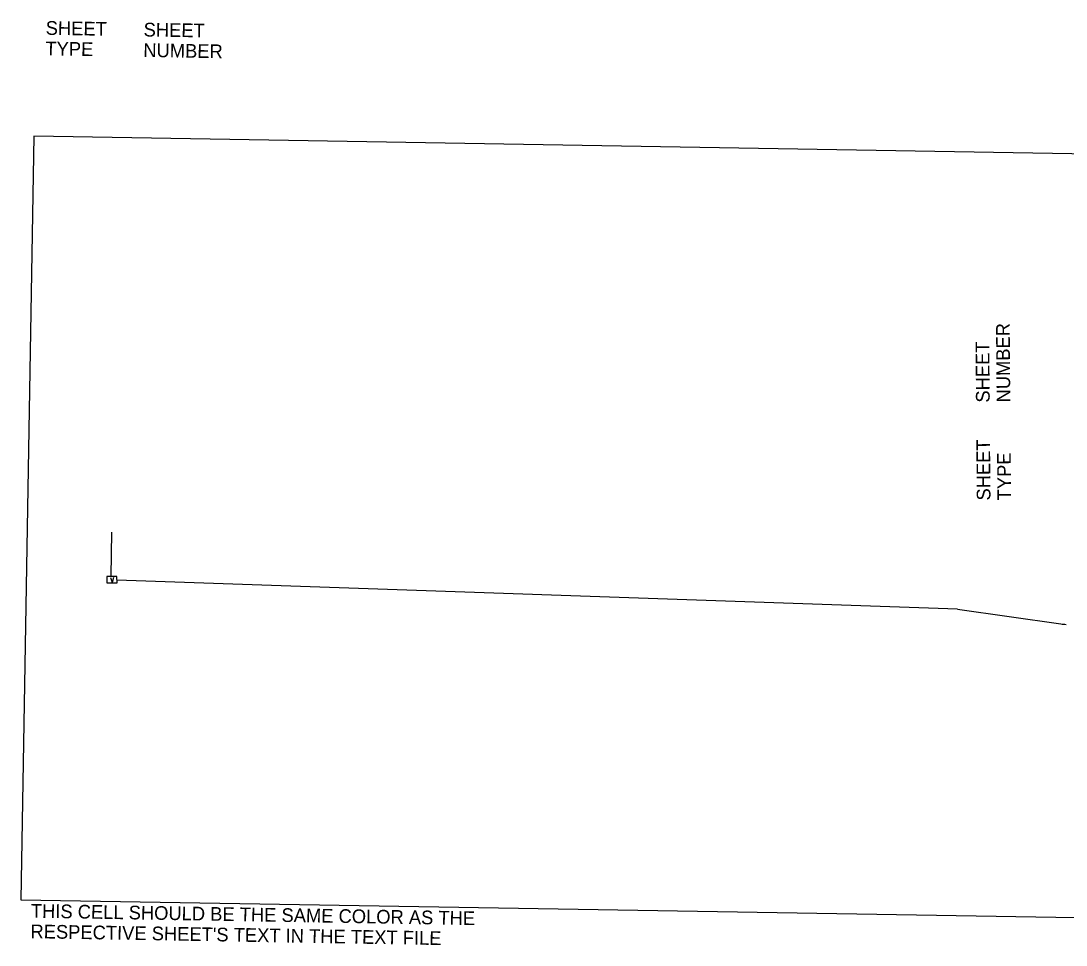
# Model space of a CAD drawing. Extents: x 601462 to 605493, y 331960 to 402715.
# Drawn here: x 602380 to 603713, y 338854 to 340034 of the extents above; entities that cross this region are included whole.
import ezdxf

# ---------------------------------------------------------------- set-up
doc = ezdxf.new("R2010")
doc.units = 0
for name, color, linetype in [('P_FTMS', 7, 'Continuous'), ('P_FTMSConduit', 7, 'Continuous'), ('P_MISC_TXT_2B (Construction)', 7, 'Continuous'), ('P_MISC_TXT_4B (Construction)', 7, 'Continuous')]:
    doc.layers.add(name, color=color, linetype=linetype)

# ---------------------------------------------------------------- blocks, each defined once
blk = doc.blocks.new('FTMS_FCV')
at = {"layer": 'P_FTMS'}
blk.add_line((12.7, 16.3), (0.6, -21.9), dxfattribs=at)
blk.add_lwpolyline([(39.1, 24.4), (-39.1, 24.4), (-39.1, -24.4), (39.1, -24.4)], close=True, dxfattribs=at)
blk.add_lwpolyline([(-12.1, 16.2), (0.6, -21.9)], dxfattribs=at)

msp = doc.modelspace()

# ---------------------------------------------------------------- linework, layer by layer
at = {"layer": 'P_FTMSConduit'}
for p, q in [((602495.2, 339380.9), (602494.4, 339324.3)), ((603574.9, 339282.5), (602502.2, 339319.6)), ((603574.9, 339282.5), (603706.8, 339263.7))]:
    msp.add_line(p, q, dxfattribs=at)
msp.add_arc((603713.8, 339313.2), 50, 261.893, 269.5524, dxfattribs=at)
at = {"layer": 'P_MISC_TXT_4B (Construction)'}
msp.add_lwpolyline([(602379.6, 338911.5), (603954.4, 338885.1), (603970.8, 339859.9), (602396, 339886.4)], close=True, dxfattribs=at)

# ---------------------------------------------------------------- block references
at = {"layer": 'P_FTMS', "xscale": 0.16404166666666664, "yscale": 0.16404166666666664, "rotation": 0.866767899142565}
msp.add_blockref('FTMS_FCV', (602495.8, 339320.3), dxfattribs=at)

# ---------------------------------------------------------------- texts
at = {"layer": 'P_MISC_TXT_2B (Construction)'}
for s, p in [('NUMBER', (603642.3, 339546.6)), ('SHEET', (603616, 339546.4)), ('SHEET', (603617, 339421.4)), ('TYPE', (603643.3, 339421.6))]:
    msp.add_text(s, height=17.5, rotation=90.4505, dxfattribs=at).set_placement(p)
at = {"layer": 'P_MISC_TXT_4B (Construction)'}
for s, p in [('SHEET', (602411.1, 340016)), ('SHEET', (602536.1, 340013.9)), ('TYPE', (602410.7, 339989.8)), ('NUMBER', (602535.7, 339987.7)), ('THIS CELL SHOULD BE THE SAME COLOR AS THE', (602392.2, 338888.7)), ("RESPECTIVE SHEET'S TEXT IN THE TEXT FILE", (602391.7, 338862.5))]:
    msp.add_text(s, height=17.5, rotation=359.0372, dxfattribs=at).set_placement(p)

doc.saveas('drawing.dxf')
